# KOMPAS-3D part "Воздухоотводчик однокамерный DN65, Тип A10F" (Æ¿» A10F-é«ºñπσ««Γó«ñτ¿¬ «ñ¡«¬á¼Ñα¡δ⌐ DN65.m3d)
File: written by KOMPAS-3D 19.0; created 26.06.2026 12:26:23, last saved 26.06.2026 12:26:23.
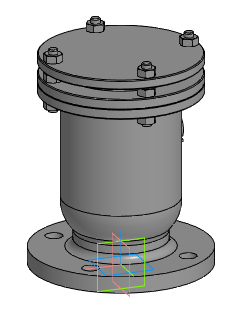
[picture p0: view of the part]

Document properties: Автор: Энергия; Полное имя файла: Z:\3.Личные\kachalov\001_3d для проектировщиков\х.х Тип A10F Воздухоотводчик однокамерный фланцевый\_step\Тип A10F-Воздухоотводчик однокамерный DN65.m3d

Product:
- Part/product: Воздухоотводчик однокамерный DN65  | designation Тип A10F

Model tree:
1. Операция без истории:1  (labels: Тип A10F; Воздухоотводчик однокамерный DN65)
